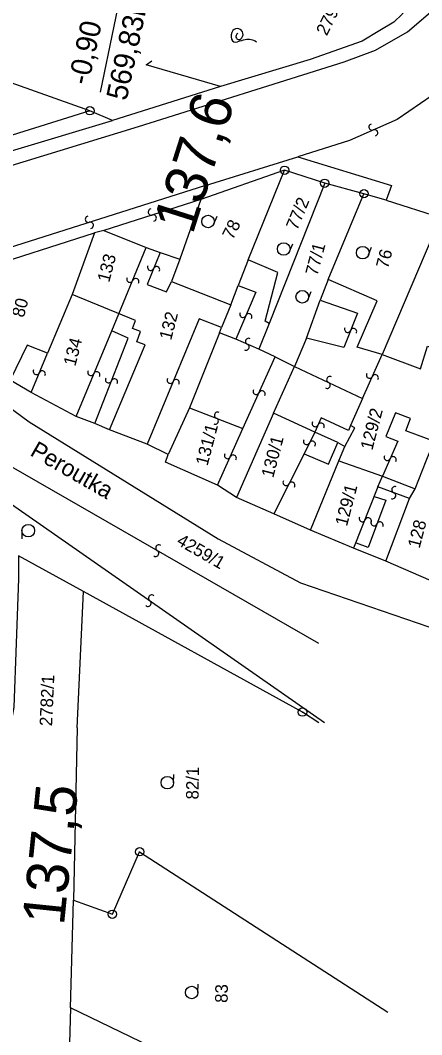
# Model space of a CAD drawing. Extents: x -658910 to -658078, y -1170373 to -1169331.
# Drawn here: x -658362.8 to -658315, y -1170036.9 to -1169916 of the extents above; entities that cross this region are included whole.
import ezdxf

# ---------------------------------------------------------------- set-up
doc = ezdxf.new("R2010")
doc.units = 0
for name, color, linetype in [('Vrstva 38', 7, 'Continuous'), ('Vrstva 39', 7, 'Continuous'), ('Vrstva 7', 7, 'Continuous'), ('Vrstva 8', 7, 'Continuous'), ('Vrstva 9', 7, 'Continuous')]:
    doc.layers.add(name, color=color, linetype=linetype)

msp = doc.modelspace()

# ---------------------------------------------------------------- linework, layer by layer
at = {"layer": 'Vrstva 38'}
msp.add_lwpolyline([(-658353.245, -1169924.56), (-658349.973, -1169908.805), (-658342.452, -1169894.397)], dxfattribs=at)
at = {"layer": 'Vrstva 39'}
for centre, radius, start, end in [((-658336.704, -1169917.878), 0.995, 139.45074, 202.16968), ((-658336.942, -1169917.675), 0.682, 305.79473, 139.45074), ((-658336.741, -1169917.922), 0.375, 115.49354, 243.54201), ((-658337.1, -1169918.04), 0.568, 202.16968, 287.93295), ((-658333.945, -1169927.79), 9.68, 102.22973, 107.93295), ((-658336.75, -1169917.941), 0.354, 243.54201, 305.79473), ((-658335.634, -1169919.995), 1.705, 55.35219, 102.22973)]:
    msp.add_arc(centre, radius, start, end, dxfattribs=at)
at = {"layer": 'Vrstva 8'}
for p, q in [((-658354.55, -1169926.789), (-658354.45, -1169926.789)), ((-658354.55, -1169926.789), (-658354.45, -1169926.789)), ((-658331.37, -1169933.879), (-658331.27, -1169933.879)), ((-658331.37, -1169933.879), (-658331.27, -1169933.879)), ((-658326.589, -1169935.43), (-658326.489, -1169935.43)), ((-658326.589, -1169935.43), (-658326.489, -1169935.43)), ((-658321.909, -1169936.67), (-658321.809, -1169936.67)), ((-658321.909, -1169936.67), (-658321.809, -1169936.67)), ((-658332.43, -1169956.1), (-658332.43, -1169956.1)), ((-658329.23, -1169998.461), (-658329.13, -1169998.461)), ((-658348.579, -1170015.158), (-658348.576, -1170015.059)), ((-658351.829, -1170022.6), (-658351.826, -1170022.501))]:
    msp.add_line(p, q, dxfattribs=at)
for points in [[(-658387.949, -1169938.809), (-658387.691, -1169939.66), (-658386.93, -1169940.059), (-658385.551, -1169939.961), (-658348.719, -1169928.68), (-658324.219, -1169920.969), (-658320.5, -1169919.58), (-658316.68, -1169917.379), (-658311.98, -1169913.33), (-658308.27, -1169907.711), (-658290.262, -1169872.99), (-658247.48, -1169792.15)], [(-658241.422, -1169797.309), (-658274.379, -1169859.65), (-658298.41, -1169905.359), (-658299.328, -1169904.949), (-658306.441, -1169918.719), (-658309.219, -1169921.43), (-658312.328, -1169924.01), (-658317.922, -1169927.83), (-658323.578, -1169930.32), (-658329.719, -1169932.26), (-658318.578, -1169935.711), (-658319.199, -1169937.449), (-658321.859, -1169936.67), (-658326.539, -1169935.43), (-658331.32, -1169933.879), (-658341.281, -1169937.379)], [(-658316.441, -1169913.73), (-658317.309, -1169915.26), (-658318.32, -1169916.211), (-658319.961, -1169917.23), (-658322.07, -1169918.49), (-658328.25, -1169920.67), (-658338.93, -1169923.879), (-658347.781, -1169921.33), (-658347.143, -1169920.814)], [(-658338.93, -1169923.879), (-658351.82, -1169927.941), (-658354.5, -1169926.789), (-658382.238, -1169916.941), (-658384.852, -1169936.27), (-658391.102, -1169938.059)], [(-658354.5, -1169926.789), (-658384.852, -1169936.27)], [(-658391.238, -1169939.76), (-658387.949, -1169938.809), (-658351.82, -1169927.941)], [(-658340.73, -1169935.691), (-658329.719, -1169932.26)], [(-658333.141, -1169952.129), (-658333.629, -1169951.879), (-658332.102, -1169946.051), (-658335.66, -1169944.551), (-658331.32, -1169933.879)], [(-658340.73, -1169935.691), (-658368.422, -1169944.48), (-658370.379, -1169945.641), (-658371.59, -1169946.93)], [(-658326.539, -1169935.43), (-658333.141, -1169952.129), (-658334.398, -1169955.219)], [(-658341.281, -1169937.379), (-658352.852, -1169941.039)], [(-658341.281, -1169937.379), (-658343.809, -1169944.469)], [(-658326.129, -1169946.891), (-658321.859, -1169936.67)], [(-658319.199, -1169937.449), (-658312.738, -1169939.5)], [(-658293.871, -1169945.059), (-658303.809, -1169941.98), (-658307.602, -1169940.809), (-658312.738, -1169939.5), (-658319.68, -1169955.85), (-658315.109, -1169957.531), (-658314.281, -1169954.85), (-658309.691, -1169956.6), (-658307.031, -1169949.66), (-658310.73, -1169948.26), (-658308.352, -1169942.6), (-658307.602, -1169940.809)], [(-658352.852, -1169941.039), (-658353.949, -1169941.33)], [(-658352.852, -1169941.039), (-658347.789, -1169943.07)], [(-658396.961, -1169955.051), (-658367.84, -1169945.77), (-658353.949, -1169941.33)], [(-658353.949, -1169941.33), (-658356.602, -1169948.67), (-658359.551, -1169955.66), (-658361.98, -1169954.711), (-658364, -1169958.9)], [(-658356.148, -1169963.211), (-658351.898, -1169953.031), (-658347.789, -1169943.07), (-658346.141, -1169943.67), (-658343.809, -1169944.469), (-658344.801, -1169947.129), (-658337.699, -1169949.91), (-658338.82, -1169952.629), (-658341.48, -1169951.59), (-658347.699, -1169966.51)], [(-658346.141, -1169943.67), (-658347.691, -1169947.5), (-658345.379, -1169948.35), (-658344.801, -1169947.129)], [(-658335.66, -1169944.551), (-658336.859, -1169947.621), (-658334.738, -1169948.391), (-658337.102, -1169954.01)], [(-658304.211, -1169987.02), (-658310.301, -1169984.43), (-658312.949, -1169983.23), (-658319.25, -1169980.49), (-658323.109, -1169978.93), (-658328.238, -1169976.76), (-658332.602, -1169974.84), (-658337.059, -1169972.879), (-658339.289, -1169971.42), (-658345.48, -1169968.67), (-658345.18, -1169967.77), (-658347.699, -1169966.51), (-658352.16, -1169964.82), (-658353.91, -1169964.08), (-658356.148, -1169963.211), (-658361.5, -1169960.359), (-658364, -1169958.9), (-658370.238, -1169954.9), (-658370.91, -1169953.039), (-658370.961, -1169950.98), (-658370.371, -1169949.07), (-658369.371, -1169947.32), (-658367.84, -1169945.77)], [(-658371.59, -1169946.93), (-658372.68, -1169949.871), (-658372.75, -1169952.789), (-658372.371, -1169954.98), (-658371.969, -1169956.309), (-658361.73, -1169963.859), (-658339.211, -1169977.82), (-658329.41, -1169983.051), (-658312.75, -1169988.77), (-658306.32, -1169991.449)], [(-658322.051, -1169961.08), (-658319.68, -1169955.85), (-658322.66, -1169954.949), (-658320.289, -1169949.449), (-658326.129, -1169946.891), (-658327.09, -1169949.35), (-658322.648, -1169950.93), (-658324.25, -1169955.02), (-658328.699, -1169953.871), (-658330.141, -1169957.27)], [(-658337.699, -1169949.91), (-658336.859, -1169947.621)], [(-658352.16, -1169964.82), (-658347.922, -1169954.699), (-658348.898, -1169954.309), (-658348.48, -1169953.09), (-658349.41, -1169952.719), (-658349.09, -1169951.781), (-658356.602, -1169948.67)], [(-658328.699, -1169953.871), (-658327.09, -1169949.35)], [(-658327.23, -1169990.289), (-658365.75, -1169968.17), (-658385.441, -1169954.58), (-658387.578, -1169953.48), (-658390.98, -1169952.609), (-658394.641, -1169952.49), (-658396.102, -1169952.879)], [(-658349.941, -1169953.879), (-658351.898, -1169953.031)], [(-658339.059, -1169953.24), (-658338.82, -1169952.629)], [(-658353.91, -1169964.08), (-658349.941, -1169953.879)], [(-658339.289, -1169971.42), (-658336.27, -1169964.67), (-658332.43, -1169956.1), (-658334.398, -1169955.219), (-658337.102, -1169954.01), (-658339.059, -1169953.24), (-658342.621, -1169962.18), (-658336.27, -1169964.67)], [(-658361.5, -1169960.359), (-658359.551, -1169955.66)], [(-658332.43, -1169956.1), (-658330.141, -1169957.27)], [(-658327.699, -1169965.08), (-658332.641, -1169962.82), (-658330.141, -1169957.27), (-658322.051, -1169961.08), (-658323.48, -1169964.32)], [(-658342.621, -1169962.18), (-658345.18, -1169967.77)], [(-658332.641, -1169962.82), (-658337.059, -1169972.879)], [(-658324.84, -1169968.5), (-658324.121, -1169966.801), (-658322.941, -1169964.59), (-658323.48, -1169964.32), (-658323.691, -1169964.879), (-658326.941, -1169963.391), (-658327.699, -1169965.08), (-658328.988, -1169967.68), (-658332.602, -1169974.84)], [(-658328.988, -1169967.68), (-658326.09, -1169968.92), (-658324.961, -1169966.309), (-658327.699, -1169965.08)], [(-658324.961, -1169966.309), (-658324.121, -1169966.801)], [(-658328.238, -1169976.76), (-658324.84, -1169968.5), (-658319.641, -1169970.32)], [(-658371.02, -1169972.691), (-658368.191, -1169970.66), (-658326.559, -1169999.691)], [(-658316.441, -1169973.02), (-658320.191, -1169971.609), (-658319.641, -1169970.32)], [(-658320.191, -1169971.609), (-658323.109, -1169978.93)], [(-658319.25, -1169980.49), (-658316.441, -1169973.02), (-658315.762, -1169971.84)], [(-658320.648, -1169972.77), (-658319.262, -1169973.211), (-658321.359, -1169978.859), (-658322.762, -1169978.309)], [(-658356, -1170000.34), (-658355.25, -1169984.07), (-658362.988, -1169979.84), (-658363.012, -1169982.58), (-658363.27, -1169990.23), (-658363.57, -1169997.859), (-658363.98, -1170000.289)], [(-658327.25, -1169999.76), (-658329.18, -1169998.461), (-658355.25, -1169984.07)], [(-658356, -1170000.34), (-658356.441, -1170020.871), (-658351.828, -1170022.551), (-658348.578, -1170015.109), (-658319.02, -1170034.24)], [(-658356.809, -1170033.711), (-658356.441, -1170020.871)], [(-658325.27, -1170050.609), (-658335.391, -1170044.09), (-658356.809, -1170033.711), (-658357.809, -1170068.961), (-658311.621, -1170088.621)]]:
    msp.add_lwpolyline(points, dxfattribs=at)
msp.add_lwpolyline([(-658313.301, -1169965.68), (-658313.359, -1169966.25), (-658316.879, -1169964.92), (-658316.309, -1169963.48), (-658318.09, -1169962.789), (-658319.238, -1169965.6), (-658317.84, -1169966.15), (-658319.641, -1169970.32), (-658315.762, -1169971.84), (-658314.449, -1169968.5)], close=True, dxfattribs=at)
for centre in [(-658354.5, -1169926.789), (-658354.5, -1169926.789), (-658331.32, -1169933.879), (-658331.32, -1169933.879), (-658326.539, -1169935.43), (-658326.539, -1169935.43), (-658321.859, -1169936.67), (-658321.859, -1169936.67), (-658329.18, -1169998.461), (-658348.578, -1170015.109), (-658351.828, -1170022.551)]:
    msp.add_circle(centre, 0.499, dxfattribs=at)
for centre, radius, start, end in [((-658320.898, -1169928.723), 0.376, 106.84404, 293.15517), ((-658320.597, -1169929.414), 0.377, 286.168, 113.83121), ((-658347.179, -1169938.85), 0.376, 100.54697, 286.8581), ((-658354.679, -1169939.719), 0.376, 100.63312, 286.94426), ((-658346.956, -1169939.57), 0.377, 279.87092, 107.53414), ((-658354.456, -1169940.439), 0.377, 279.95708, 107.62029), ((-658347.257, -1169945.444), 0.376, 150.97822, 337.28936), ((-658346.56, -1169945.731), 0.377, 330.30218, 157.9654), ((-658349.744, -1169946.863), 0.376, 150.77918, 337.09031), ((-658349.049, -1169947.152), 0.377, 330.10314, 157.76635), ((-658336.267, -1169951.049), 0.376, 150.22536, 336.53649), ((-658335.574, -1169951.344), 0.377, 329.54932, 157.21253), ((-658323.797, -1169952.827), 0.376, 151.63621, 337.94734), ((-658323.098, -1169953.106), 0.377, 330.96017, 158.62338), ((-658335.595, -1169954.277), 0.377, 58.08516, 245.74838), ((-658335.908, -1169954.962), 0.376, 238.7612, 65.07234), ((-658360.877, -1169957.861), 0.376, 150.51046, 336.8216), ((-658360.183, -1169958.154), 0.377, 329.83442, 157.49764), ((-658354.376, -1169957.971), 0.376, 150.33944, 336.65057), ((-658353.683, -1169958.266), 0.377, 329.66339, 157.32661), ((-658352.279, -1169958.839), 0.376, 151.78369, 338.09482), ((-658351.578, -1169959.116), 0.377, 331.10765, 158.77086), ((-658344.935, -1169958.902), 0.376, 150.40355, 336.71468), ((-658344.242, -1169959.195), 0.377, 329.72751, 157.39072), ((-658326.254, -1169959.508), 0.376, 237.81949, 64.13063), ((-658325.929, -1169958.829), 0.377, 57.14345, 244.80666), ((-658321.2, -1169958.301), 0.376, 148.64445, 334.95559), ((-658320.515, -1169958.616), 0.377, 327.96841, 155.63163), ((-658334.693, -1169960.233), 0.376, 148.90813, 335.21926), ((-658334.008, -1169960.544), 0.377, 328.23209, 155.8953), ((-658339.299, -1169963.081), 0.376, 61.65248, 247.96362), ((-658339.578, -1169963.78), 0.377, 240.97644, 68.63966), ((-658327.66, -1169964.07), 0.376, 148.55123, 334.86237), ((-658326.977, -1169964.386), 0.377, 327.87519, 155.53841), ((-658328.687, -1169966.208), 0.376, 146.68941, 333.00054), ((-658328.014, -1169966.546), 0.377, 326.01337, 153.67658), ((-658338.111, -1169967.881), 0.376, 148.91724, 335.22837), ((-658337.426, -1169968.192), 0.377, 328.2412, 155.90441), ((-658319.082, -1169968.087), 0.376, 149.7737, 336.08483), ((-658318.391, -1169968.388), 0.377, 329.09766, 156.76087), ((-658331.135, -1169971.086), 0.376, 146.26553, 332.57667), ((-658330.464, -1169971.429), 0.377, 325.58949, 153.25271), ((-658318.453, -1169972.661), 0.377, 241.6676, 69.33081), ((-658318.182, -1169971.958), 0.376, 62.34364, 248.65478), ((-658322.049, -1169975.4), 0.376, 152.16769, 338.47882), ((-658321.347, -1169975.673), 0.377, 331.49164, 159.15486), ((-658320.66, -1169975.895), 0.376, 152.61333, 338.92447), ((-658319.955, -1169976.162), 0.377, 331.93729, 159.60051), ((-658346.292, -1169978.903), 0.377, 52.48198, 240.14519), ((-658346.671, -1169979.554), 0.376, 233.15802, 59.46915), ((-658347.155, -1169984.871), 0.377, 47.46762, 235.13084), ((-658347.589, -1169985.486), 0.376, 228.14367, 54.4548)]:
    msp.add_arc(centre, radius, start, end, dxfattribs=at)
at = {"layer": 'Vrstva 9'}
for p, q in [((-658339.731, -1169940.274), (-658339.346, -1169939.352)), ((-658330.719, -1169943.549), (-658330.334, -1169942.627)), ((-658321.308, -1169943.974), (-658320.944, -1169943.043)), ((-658328.516, -1169949.248), (-658328.131, -1169948.326)), ((-658362.59, -1169976.83), (-658362.595, -1169977.829)), ((-658344.533, -1170006.88), (-658344.521, -1170005.881)), ((-658341.63, -1170031.896), (-658341.618, -1170030.897))]:
    msp.add_line(p, q, dxfattribs=at)
for centre in [(-658340.424, -1169939.985), (-658331.412, -1169943.26), (-658322.007, -1169943.701), (-658329.209, -1169948.959), (-658361.84, -1169976.834), (-658345.283, -1170006.871), (-658342.38, -1170031.887)]:
    msp.add_circle(centre, 0.75, dxfattribs=at)

# ---------------------------------------------------------------- texts
at = {"layer": 'Vrstva 39'}
for s, p in [('569,83m', (-658350.146, -1169925.685)), ('-0,90', (-658354.68, -1169923.823))]:
    msp.add_text(s, height=2.5, rotation=77.77125, dxfattribs=at).set_placement(p)
at = {"layer": 'Vrstva 7'}
for s, rotation, p in [('137,6', 72.34238, (-658342.28, -1169941.649)), ('137,5', 84.16119, (-658357.598, -1170023.976))]:
    msp.add_text(s, height=4.999, rotation=rotation, dxfattribs=at).set_placement(p)
at = {"layer": 'Vrstva 9'}
for s, height, rotation, p in [('2791', 1.5, 63.88515, (-658326.289, -1169917.933)), ('77/2', 1.5, 67.3281, (-658329.828, -1169941.113)), ('78', 1.5, 63.88515, (-658337.481, -1169942.25)), ('77/1', 1.5, 75.37005, (-658327.421, -1169946.529)), ('76', 1.5, 75.37005, (-658319.014, -1169945.676)), ('133', 1.5, 75.37005, (-658352.202, -1169947.319)), ('80', 1.5, 75.37005, (-658362.375, -1169951.514)), ('132', 1.5, 75.37005, (-658344.83, -1169954.209)), ('134', 1.5, 75.37005, (-658356.245, -1169957.319)), ('129/2', 1.5, 75.37005, (-658320.866, -1169967.329)), ('131/1', 1.5, 75.37005, (-658340.493, -1169969.182)), ('Peroutka', 2, 330.12765, (-658361.75, -1169967.801)), ('130/1', 1.5, 75.37005, (-658332.672, -1169970.619)), ('129/1', 1.5, 75.37005, (-658323.885, -1169976.382)), ('128', 1.5, 75.37005, (-658315.236, -1169979.015)), ('4259/1', 1.5, 330.12765, (-658344.281, -1169978.42)), ('2782/1', 1.5, 87.3603, (-658359.01, -1170000.165)), ('82/1', 1.5, 89.30079, (-658341.558, -1170008.884)), ('83', 1.5, 89.30079, (-658338.097, -1170033.126))]:
    msp.add_text(s, height=height, rotation=rotation, dxfattribs=at).set_placement(p)

doc.saveas('drawing.dxf')
